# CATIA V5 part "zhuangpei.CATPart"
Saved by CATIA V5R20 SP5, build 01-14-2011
Part number: 套
Material "Slightly Cloudy"
Bounding box of the stored display mesh (mm): x -80 to 80, y -79.813 to 79.813, z -15 to 15
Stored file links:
  E:\scc\zhuangpei.CATPart
  C:\Program Files\Dassault Systemes\B20\intel_a\startup\materials\Catalog.CATMaterial
  C:\Program Files\Dassault Systemes\B20\intel_a\startup\materials\summer_sky.jpg
  Part1.CATPart
  C:\Program Files\Dassault Systemes\B20\intel_a\startup\materials\DS_star.jpg
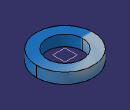
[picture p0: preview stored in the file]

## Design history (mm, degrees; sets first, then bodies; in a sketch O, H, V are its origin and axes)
External parameters (linked from other documents)
  `External.长度.1` = 50 mm
Body1 (main body), material "Slightly Cloudy"
  Sketch1 on xy-plane, origin (0, 0, 0), H (1, 0, 0), V (0, 1, 0)
    circle A1 centre (0, 0) radius 50
    circle A2 centre (0, 0) radius 80
    radius A1 = 50 {= `External.长度.1`}
    radius A2 = 80 {= `External.长度.1` +30mm}
  Pad1: profile Sketch1, direction (0, 0, 1), length 15, mirrored extent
